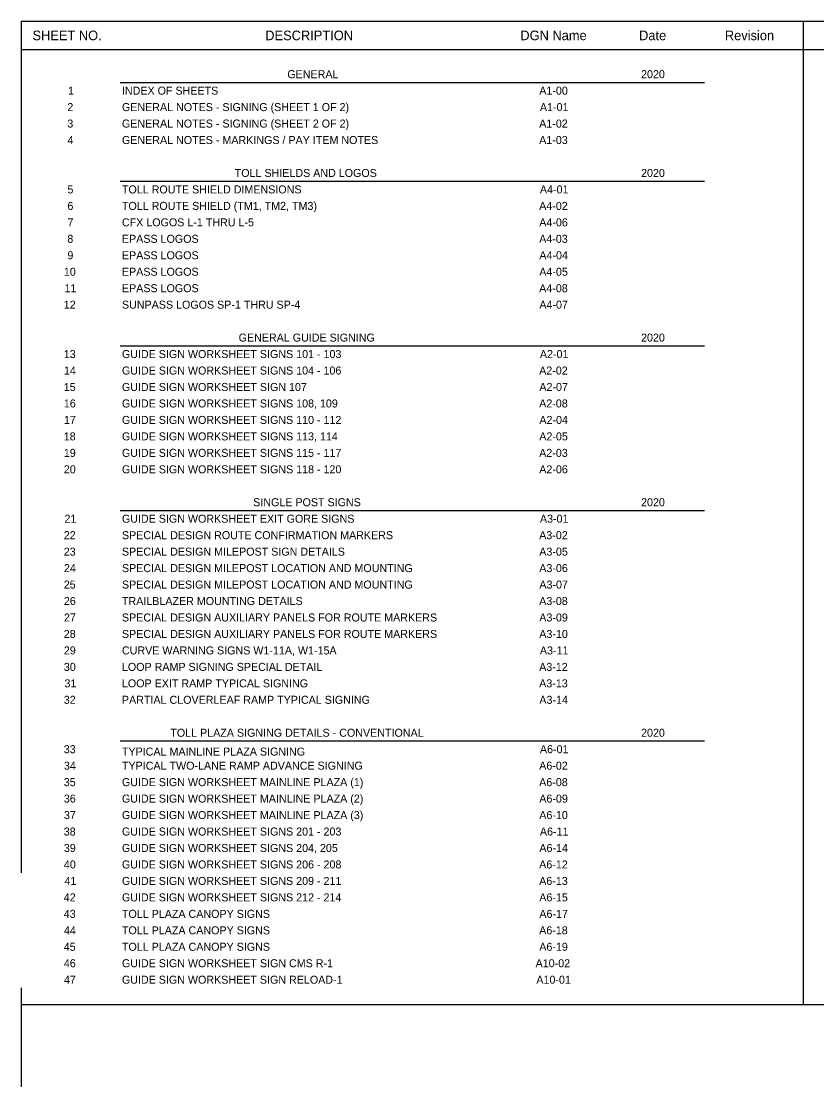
# Model space of a CAD drawing. Extents: x 2479979.8 to 2480018.9, y 3680687.9 to 3680700.6.
# Drawn here: x 2480001.46 to 2480010.15, y 3680688.91 to 3680700.55 of the extents above; entities that cross this region are included whole.
import ezdxf

# ---------------------------------------------------------------- set-up
doc = ezdxf.new("R2010")
doc.units = 0
doc.layers.add('SumBoxLines_dp', color=7, linetype='Continuous')
doc.layers.add('TextLabel', color=7, linetype='Continuous')

msp = doc.modelspace()

# ---------------------------------------------------------------- linework, layer by layer
at = {"layer": 'SumBoxLines_dp'}
for p, q in [((2480001.458, 3680700.555), (2480018.85, 3680700.555)), ((2480001.458, 3680700.555), (2480001.458, 3680691.247)), ((2480010.008, 3680700.555), (2480010.008, 3680689.807)), ((2480001.458, 3680700.247), (2480018.85, 3680700.247)), ((2480001.458, 3680700.247), (2480018.85, 3680700.247)), ((2480010.008, 3680700.247), (2480010.008, 3680691.427)), ((2480002.538, 3680699.887), (2480008.928, 3680699.887)), ((2480002.538, 3680699.887), (2480008.928, 3680699.887)), ((2480002.538, 3680698.807), (2480008.928, 3680698.807)), ((2480002.538, 3680698.807), (2480008.928, 3680698.807)), ((2480002.538, 3680697.007), (2480008.928, 3680697.007)), ((2480002.538, 3680697.007), (2480008.928, 3680697.007)), ((2480002.538, 3680695.207), (2480008.928, 3680695.207)), ((2480002.538, 3680695.207), (2480008.928, 3680695.207)), ((2480002.538, 3680692.687), (2480008.928, 3680692.687)), ((2480002.538, 3680692.687), (2480008.928, 3680692.687)), ((2480001.458, 3680689.987), (2480001.458, 3680688.907)), ((2480001.458, 3680689.807), (2480018.85, 3680689.807)), ((2480001.458, 3680689.807), (2480018.85, 3680689.807))]:
    msp.add_line(p, q, dxfattribs=at)

# ---------------------------------------------------------------- texts
at = {"layer": 'TextLabel'}
for s, height, p in [('SHEET NO.', 0.105, (2480001.58, 3680700.348)), ('DESCRIPTION', 0.105, (2480004.125, 3680700.348)), ('DGN Name', 0.105, (2480006.914, 3680700.348)), ('Date', 0.105, (2480008.212, 3680700.348)), ('Revision', 0.105, (2480009.15, 3680700.348)), ('GENERAL', 0.0875, (2480004.366, 3680699.933)), ('2020', 0.0875, (2480008.234, 3680699.933)), ('1', 0.0875, (2480001.969, 3680699.753)), ('INDEX OF SHEETS', 0.0875, (2480002.558, 3680699.753)), ('A1-00', 0.0875, (2480007.121, 3680699.753)), ('2', 0.0875, (2480001.961, 3680699.573)), ('GENERAL NOTES - SIGNING (SHEET 1 OF 2)', 0.0875, (2480002.558, 3680699.573)), ('A1-01', 0.0875, (2480007.128, 3680699.573)), ('3', 0.0875, (2480001.961, 3680699.393)), ('GENERAL NOTES - SIGNING (SHEET 2 OF 2)', 0.0875, (2480002.558, 3680699.393)), ('A1-02', 0.0875, (2480007.12, 3680699.393)), ('4', 0.0875, (2480001.963, 3680699.213)), ('GENERAL NOTES - MARKINGS / PAY ITEM NOTES', 0.0875, (2480002.558, 3680699.213)), ('A1-03', 0.0875, (2480007.12, 3680699.213)), ('TOLL SHIELDS AND LOGOS', 0.0875, (2480003.791, 3680698.853)), ('2020', 0.0875, (2480008.234, 3680698.853)), ('5', 0.0875, (2480001.962, 3680698.673)), ('TOLL ROUTE SHIELD DIMENSIONS', 0.0875, (2480002.558, 3680698.673)), ('A4-01', 0.0875, (2480007.128, 3680698.673)), ('6', 0.0875, (2480001.962, 3680698.493)), ('TOLL ROUTE SHIELD (TM1, TM2, TM3)', 0.0875, (2480002.558, 3680698.493)), ('A4-02', 0.0875, (2480007.12, 3680698.493)), ('7', 0.0875, (2480001.963, 3680698.313)), ('CFX LOGOS L-1 THRU L-5', 0.0875, (2480002.558, 3680698.313)), ('A4-06', 0.0875, (2480007.121, 3680698.313)), ('8', 0.0875, (2480001.961, 3680698.133)), ('EPASS LOGOS', 0.0875, (2480002.558, 3680698.133)), ('A4-03', 0.0875, (2480007.12, 3680698.133)), ('9', 0.0875, (2480001.962, 3680697.953)), ('EPASS LOGOS', 0.0875, (2480002.558, 3680697.953)), ('A4-04', 0.0875, (2480007.122, 3680697.953)), ('10', 0.0875, (2480001.923, 3680697.773)), ('EPASS LOGOS', 0.0875, (2480002.558, 3680697.773)), ('A4-05', 0.0875, (2480007.121, 3680697.773)), ('11', 0.0875, (2480001.93, 3680697.593)), ('EPASS LOGOS', 0.0875, (2480002.558, 3680697.593)), ('A4-08', 0.0875, (2480007.12, 3680697.593)), ('12', 0.0875, (2480001.922, 3680697.413)), ('SUNPASS LOGOS SP-1 THRU SP-4', 0.0875, (2480002.558, 3680697.413)), ('A4-07', 0.0875, (2480007.122, 3680697.413)), ('GENERAL GUIDE SIGNING', 0.0875, (2480003.834, 3680697.053)), ('2020', 0.0875, (2480008.234, 3680697.053)), ('13', 0.0875, (2480001.922, 3680696.873)), ('GUIDE SIGN WORKSHEET SIGNS 101 - 103', 0.0875, (2480002.558, 3680696.873)), ('A2-01', 0.0875, (2480007.128, 3680696.873)), ('14', 0.0875, (2480001.924, 3680696.693)), ('GUIDE SIGN WORKSHEET SIGNS 104 - 106', 0.0875, (2480002.558, 3680696.693)), ('A2-02', 0.0875, (2480007.12, 3680696.693)), ('15', 0.0875, (2480001.922, 3680696.513)), ('GUIDE SIGN WORKSHEET SIGN 107', 0.0875, (2480002.558, 3680696.513)), ('A2-07', 0.0875, (2480007.122, 3680696.513)), ('16', 0.0875, (2480001.923, 3680696.333)), ('GUIDE SIGN WORKSHEET SIGNS 108, 109', 0.0875, (2480002.558, 3680696.333)), ('A2-08', 0.0875, (2480007.12, 3680696.333)), ('17', 0.0875, (2480001.924, 3680696.153)), ('GUIDE SIGN WORKSHEET SIGNS 110 - 112', 0.0875, (2480002.558, 3680696.153)), ('A2-04', 0.0875, (2480007.122, 3680696.153)), ('18', 0.0875, (2480001.922, 3680695.973)), ('GUIDE SIGN WORKSHEET SIGNS 113, 114', 0.0875, (2480002.558, 3680695.973)), ('A2-05', 0.0875, (2480007.121, 3680695.973)), ('19', 0.0875, (2480001.923, 3680695.793)), ('GUIDE SIGN WORKSHEET SIGNS 115 - 117', 0.0875, (2480002.558, 3680695.793)), ('A2-03', 0.0875, (2480007.12, 3680695.793)), ('20', 0.0875, (2480001.923, 3680695.613)), ('GUIDE SIGN WORKSHEET SIGNS 118 - 120', 0.0875, (2480002.558, 3680695.613)), ('A2-06', 0.0875, (2480007.121, 3680695.613)), ('SINGLE POST SIGNS', 0.0875, (2480003.993, 3680695.253)), ('2020', 0.0875, (2480008.234, 3680695.253)), ('21', 0.0875, (2480001.93, 3680695.073)), ('GUIDE SIGN WORKSHEET EXIT GORE SIGNS', 0.0875, (2480002.558, 3680695.073)), ('A3-01', 0.0875, (2480007.128, 3680695.073)), ('22', 0.0875, (2480001.922, 3680694.893)), ('SPECIAL DESIGN ROUTE CONFIRMATION MARKERS', 0.0875, (2480002.558, 3680694.893)), ('A3-02', 0.0875, (2480007.12, 3680694.893)), ('23', 0.0875, (2480001.922, 3680694.713)), ('SPECIAL DESIGN MILEPOST SIGN DETAILS', 0.0875, (2480002.558, 3680694.713)), ('A3-05', 0.0875, (2480007.121, 3680694.713)), ('24', 0.0875, (2480001.924, 3680694.533)), ('SPECIAL DESIGN MILEPOST LOCATION AND MOUNTING', 0.0875, (2480002.558, 3680694.533)), ('A3-06', 0.0875, (2480007.121, 3680694.533)), ('25', 0.0875, (2480001.922, 3680694.353)), ('SPECIAL DESIGN MILEPOST LOCATION AND MOUNTING', 0.0875, (2480002.558, 3680694.353)), ('A3-07', 0.0875, (2480007.122, 3680694.353)), ('26', 0.0875, (2480001.923, 3680694.173)), ('TRAILBLAZER MOUNTING DETAILS', 0.0875, (2480002.558, 3680694.173)), ('A3-08', 0.0875, (2480007.12, 3680694.173)), ('27', 0.0875, (2480001.924, 3680693.993)), ('SPECIAL DESIGN AUXILIARY PANELS FOR ROUTE MARKERS', 0.0875, (2480002.558, 3680693.993)), ('A3-09', 0.0875, (2480007.121, 3680693.993)), ('28', 0.0875, (2480001.922, 3680693.813)), ('SPECIAL DESIGN AUXILIARY PANELS FOR ROUTE MARKERS', 0.0875, (2480002.558, 3680693.813)), ('A3-10', 0.0875, (2480007.121, 3680693.813)), ('29', 0.0875, (2480001.923, 3680693.633)), ('CURVE WARNING SIGNS W1-11A, W1-15A', 0.0875, (2480002.558, 3680693.633)), ('A3-11', 0.0875, (2480007.128, 3680693.633)), ('30', 0.0875, (2480001.923, 3680693.453)), ('LOOP RAMP SIGNING SPECIAL DETAIL', 0.0875, (2480002.558, 3680693.453)), ('A3-12', 0.0875, (2480007.12, 3680693.453)), ('31', 0.0875, (2480001.93, 3680693.273)), ('LOOP EXIT RAMP TYPICAL SIGNING', 0.0875, (2480002.558, 3680693.273)), ('A3-13', 0.0875, (2480007.12, 3680693.273)), ('32', 0.0875, (2480001.922, 3680693.093)), ('PARTIAL CLOVERLEAF RAMP TYPICAL SIGNING', 0.0875, (2480002.558, 3680693.093)), ('A3-14', 0.0875, (2480007.122, 3680693.093)), ('TOLL PLAZA SIGNING DETAILS - CONVENTIONAL', 0.0875, (2480003.087, 3680692.733)), ('2020', 0.0875, (2480008.234, 3680692.733)), ('33', 0.0875, (2480001.922, 3680692.553)), ('TYPICAL MAINLINE PLAZA SIGNING', 0.0875, (2480002.558, 3680692.527)), ('A6-01', 0.0875, (2480007.128, 3680692.553)), ('34', 0.0875, (2480001.924, 3680692.373)), ('TYPICAL TWO-LANE RAMP ADVANCE SIGNING', 0.0875, (2480002.558, 3680692.373)), ('A6-02', 0.0875, (2480007.12, 3680692.373)), ('35', 0.0875, (2480001.922, 3680692.193)), ('GUIDE SIGN WORKSHEET MAINLINE PLAZA (1)', 0.0875, (2480002.558, 3680692.193)), ('A6-08', 0.0875, (2480007.12, 3680692.193)), ('36', 0.0875, (2480001.923, 3680692.013)), ('GUIDE SIGN WORKSHEET MAINLINE PLAZA (2)', 0.0875, (2480002.558, 3680692.013)), ('A6-09', 0.0875, (2480007.121, 3680692.013)), ('37', 0.0875, (2480001.924, 3680691.833)), ('GUIDE SIGN WORKSHEET MAINLINE PLAZA (3)', 0.0875, (2480002.558, 3680691.833)), ('A6-10', 0.0875, (2480007.121, 3680691.833)), ('38', 0.0875, (2480001.922, 3680691.653)), ('GUIDE SIGN WORKSHEET SIGNS 201 - 203', 0.0875, (2480002.558, 3680691.653)), ('A6-11', 0.0875, (2480007.128, 3680691.653)), ('39', 0.0875, (2480001.923, 3680691.473)), ('GUIDE SIGN WORKSHEET SIGNS 204, 205', 0.0875, (2480002.558, 3680691.473)), ('A6-14', 0.0875, (2480007.122, 3680691.473)), ('40', 0.0875, (2480001.923, 3680691.293)), ('GUIDE SIGN WORKSHEET SIGNS 206 - 208', 0.0875, (2480002.558, 3680691.293)), ('A6-12', 0.0875, (2480007.12, 3680691.293)), ('41', 0.0875, (2480001.93, 3680691.113)), ('GUIDE SIGN WORKSHEET SIGNS 209 - 211', 0.0875, (2480002.558, 3680691.113)), ('A6-13', 0.0875, (2480007.12, 3680691.113)), ('42', 0.0875, (2480001.922, 3680690.933)), ('GUIDE SIGN WORKSHEET SIGNS 212 - 214', 0.0875, (2480002.558, 3680690.933)), ('A6-15', 0.0875, (2480007.121, 3680690.933)), ('43', 0.0875, (2480001.922, 3680690.753)), ('TOLL PLAZA CANOPY SIGNS', 0.0875, (2480002.558, 3680690.753)), ('A6-17', 0.0875, (2480007.122, 3680690.753)), ('44', 0.0875, (2480001.924, 3680690.573)), ('TOLL PLAZA CANOPY SIGNS', 0.0875, (2480002.558, 3680690.573)), ('A6-18', 0.0875, (2480007.12, 3680690.573)), ('45', 0.0875, (2480001.922, 3680690.393)), ('TOLL PLAZA CANOPY SIGNS', 0.0875, (2480002.558, 3680690.393)), ('A6-19', 0.0875, (2480007.121, 3680690.393)), ('46', 0.0875, (2480001.923, 3680690.213)), ('GUIDE SIGN WORKSHEET SIGN CMS R-1', 0.0875, (2480002.558, 3680690.213)), ('A10-02', 0.0875, (2480007.081, 3680690.213)), ('47', 0.0875, (2480001.924, 3680690.033)), ('GUIDE SIGN WORKSHEET SIGN RELOAD-1', 0.0875, (2480002.558, 3680690.033)), ('A10-01', 0.0875, (2480007.089, 3680690.033))]:
    msp.add_text(s, height=height, dxfattribs=at).set_placement(p)

doc.saveas('drawing.dxf')
